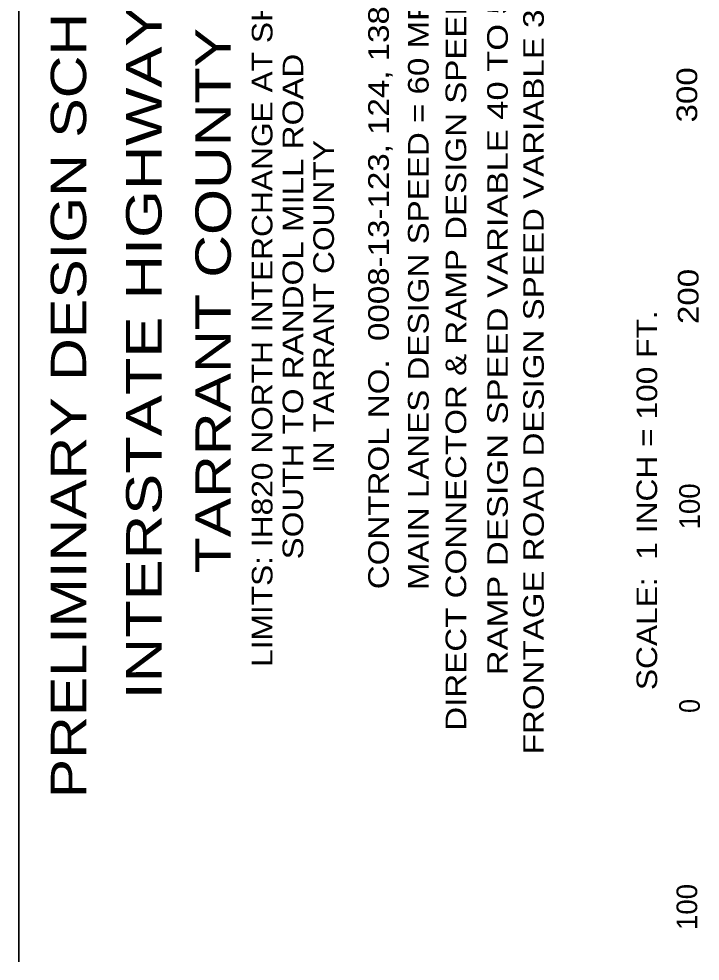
# Model space of a CAD drawing. Extents: x 2363323 to 2367082, y 6956018 to 6980837.
# Drawn here: x 2366226.5 to 2366563.3, y 6979505.4 to 6979971.5 of the extents above; entities that cross this region are included whole.
import ezdxf
from ezdxf.enums import TextEntityAlignment as Align

# ---------------------------------------------------------------- set-up
doc = ezdxf.new("R2010")
doc.units = 0
doc.header["$LTSCALE"] = 4.1
for name, color, linetype, lineweight in [('61', 7, 'Continuous', 40), ('62', 7, 'Continuous', 13), ('63', 7, 'Continuous', 13)]:
    doc.layers.add(name, color=color, linetype=linetype, lineweight=lineweight)

msp = doc.modelspace()

# ---------------------------------------------------------------- linework, layer by layer
at = {"layer": '62', "lineweight": 35}
msp.add_line((2366226.483, 6979505.057), (2366226.482, 6980156.078), dxfattribs=at)
at = {"layer": '63', "lineweight": 35}
msp.add_line((2366226.483, 6979505.057), (2366226.482, 6980156.078), dxfattribs=at)

# ---------------------------------------------------------------- texts
at = {"layer": '61'}
for s, width, p in [('LIMITS: IH820 NORTH INTERCHANGE AT SH121', 1.15, (2366351.869, 6979829.154)), ('SOUTH TO RANDOL MILL ROAD', 1.2, (2366367.069, 6979829.154)), ('IN TARRANT COUNTY', 1.15, (2366382.269, 6979829.154))]:
    msp.add_text(s, height=10.2, rotation=90, dxfattribs=dict(at, width=width)).set_placement(p, align=Align.CENTER)
at = {"layer": '62'}
for s, height, width, p in [('PRELIMINARY DESIGN SCHEMATIC', 17.5, 1.25, (2366259.764, 6979585.947)), ('INTERSTATE HIGHWAY 820', 17.5, 1.3, (2366297.009, 6979634.899)), ('CONTROL NO.  0008-13-123, 124, 138', 10.2, 1.2, (2366409.412, 6979689.355)), ('TARRANT COUNTY', 17.5, 1.25, (2366331.264, 6979697.168))]:
    msp.add_text(s, height=height, rotation=90, dxfattribs=dict(at, width=width)).set_placement(p)
for s, width, p in [('FRONTAGE ROAD DESIGN SPEED VARIABLE 35 TO 40 MPH', 1.2, (2366486.028, 6979841.915)), ('DIRECT CONNECTOR & RAMP DESIGN SPEED = 50 MPH', 1.2, (2366447.657, 6979841.038)), ('RAMP DESIGN SPEED VARIABLE 40 TO 50 MPH', 1.25, (2366468.233, 6979841.038)), ('MAIN LANES DESIGN SPEED = 60 MPH', 1.2, (2366429.079, 6979841.039)), ('300', 1.2, (2366561.864, 6979933.851)), ('200', 1.2, (2366562.514, 6979834.166)), ('SCALE:  1 INCH = 100 FT.', 1.15, (2366542.063, 6979733.391)), ('0', 0.9, (2366563.171, 6979631.623))]:
    msp.add_text(s, height=10.2, rotation=90, dxfattribs=dict(at, width=width)).set_placement(p, align=Align.CENTER)
for p in [(2366563.176, 6979730.33), (2366561.848, 6979532.211)]:
    msp.add_text('100', height=10.2, rotation=90, dxfattribs=at).set_placement(p, align=Align.CENTER)
at = {"layer": '63'}
for s, width, p in [('DIRECT CONNECTOR & RAMP DESIGN SPEED = 50 MPH', 1.2, (2366447.657, 6979841.038)), ('MAIN LANES DESIGN SPEED = 60 MPH', 1.2, (2366429.079, 6979841.039)), ('300', 1.2, (2366561.864, 6979933.851)), ('200', 1.2, (2366562.514, 6979834.166)), ('0', 0.9, (2366563.171, 6979631.623))]:
    msp.add_text(s, height=10.2, rotation=90, dxfattribs=dict(at, width=width)).set_placement(p, align=Align.CENTER)
for p in [(2366563.176, 6979730.33), (2366561.848, 6979532.211)]:
    msp.add_text('100', height=10.2, rotation=90, dxfattribs=at).set_placement(p, align=Align.CENTER)

doc.saveas('drawing.dxf')
